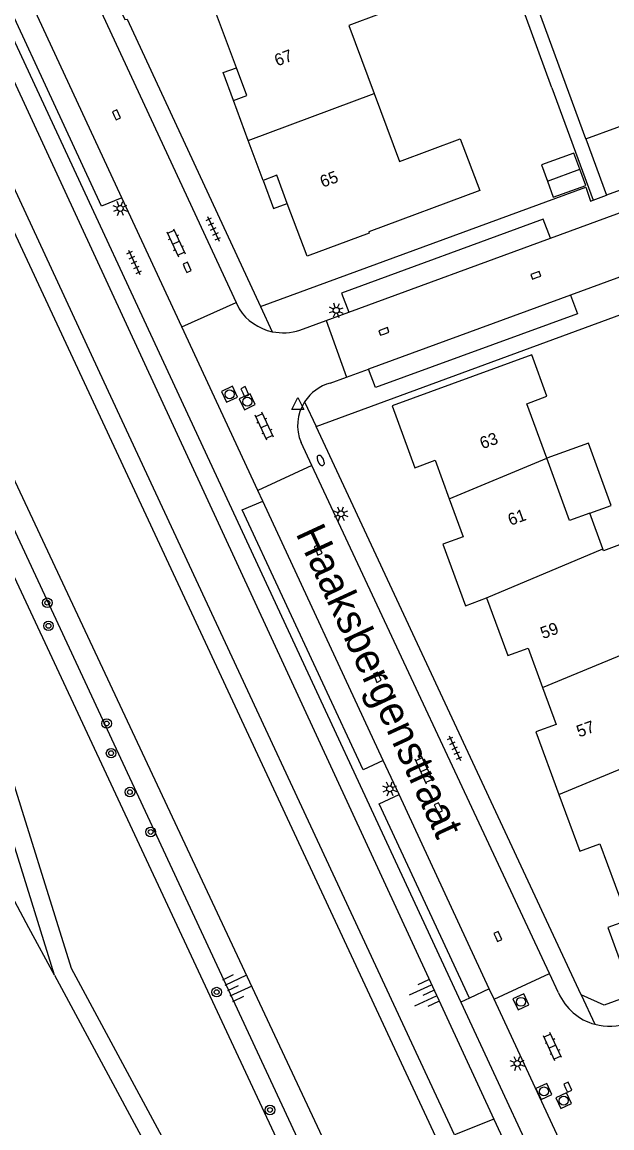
# Model space of a CAD drawing. Extents: x 128000 to 131008, y 398996 to 402500.
# Drawn here: x 128199.6 to 128248.8, y 399087 to 399179.2 of the extents above; entities that cross this region are included whole.
import ezdxf

# ---------------------------------------------------------------- set-up
doc = ezdxf.new("R2010")
doc.units = 0
for name, color, linetype in [('gg-afsc-erfafscheiding', 7, 'Continuous'), ('gg-anno-huisnummerreeks BGT', 7, 'Continuous'), ('gg-anno-openbare ruimte label', 7, 'Continuous'), ('gg-bbg-gedigitaliseerde bebouwing', 7, 'Continuous'), ('gg-bbg-gedigitaliseerde bijgebouw', 7, 'Continuous'), ('gg-bbg-hoofdgebouw', 7, 'Continuous'), ('gg-bbg-luifel en loopbrug', 7, 'Continuous'), ('gg-bbg-tussenscheiding', 7, 'Continuous'), ('gg-knt-BGT kruinlijn', 7, 'Continuous'), ('gg-knt-bovenkant onderkant talud', 7, 'Continuous'), ('gg-knt-verharding', 7, 'Continuous'), ('gg-knt-verharding nz', 7, 'Continuous'), ('gg-kntw-beschoeiing', 7, 'Continuous'), ('gt-grn-groengrens', 7, 'Continuous'), ('gt-grn-weggrens', 7, 'Continuous'), ('gt-symb-boom', 7, 'Continuous'), ('gt-symb-brandkraan', 7, 'Continuous'), ('gt-symb-klinker verharding', 7, 'Continuous'), ('gt-symb-kolk', 7, 'Continuous'), ('gt-symb-lichtmast', 7, 'Continuous'), ('gt-symb-rioolschacht', 7, 'Continuous'), ('gt-symb-talud symbool', 7, 'Continuous'), ('gt-symb-tegel verharding', 7, 'Continuous'), ('gt-symb-waterafsluiter', 7, 'Continuous')]:
    doc.layers.add(name, color=color, linetype=linetype)

# ---------------------------------------------------------------- blocks, each defined once
blk = doc.blocks.new('gt0-KOLK')
at = {"layer": 'gt-symb-kolk'}
blk.add_lwpolyline([(0, 0), (0.375, 0), (0.375, 0.4), (-0.375, 0.4), (-0.375, 0), (0, 0)], dxfattribs=at)
blk = doc.blocks.new('gt0-LMAST')
at = {"layer": 'gt-symb-lichtmast'}
for p, q in [((-0.182, 0.173), (-0.447, 0.438)), ((-0.005, 0.246), (-0.005, 0.621)), ((0.172, 0.173), (0.437, 0.438)), ((-0.255, -0.004), (-0.63, -0.004)), ((-0.182, -0.181), (-0.447, -0.446)), ((-0.005, -0.254), (-0.005, -0.629)), ((0.437, -0.446), (0.172, -0.181)), ((0.245, -0.004), (0.62, -0.004))]:
    blk.add_line(p, q, dxfattribs=at)
blk.add_circle((-0.005, -0.004), 0.25, dxfattribs=at)
blk = doc.blocks.new('gt0-TEG1')
at = {"layer": 'gt-symb-tegel verharding'}
for p, q in [((-1.125, 0), (1.125, 0)), ((-0.9, -0.25), (-0.9, 0.25)), ((-0.45, -0.25), (-0.45, 0.25)), ((0, -0.25), (0, 0.25)), ((0.45, -0.25), (0.45, 0.25)), ((0.9, -0.25), (0.9, 0.25))]:
    blk.add_line(p, q, dxfattribs=at)
blk = doc.blocks.new('gt0-KL1')
at = {"layer": 'gt-symb-klinker verharding'}
for p, q in [((-1.15, 0.3), (1.15, 0.3)), ((-1, -0.3), (-1, 0.3)), ((-0.5, 0.3), (-0.5, 0.45)), ((0, -0.3), (0, 0.3)), ((0.5, 0.3), (0.5, 0.45)), ((1, -0.3), (1, 0.3)), ((-1.15, -0.3), (1.15, -0.3)), ((-0.5, -0.45), (-0.5, -0.3)), ((0.5, -0.45), (0.5, -0.3))]:
    blk.add_line(p, q, dxfattribs=at)
blk = doc.blocks.new('gt0-WAFSL')
at = {"layer": 'gt-symb-waterafsluiter'}
for p, q in [((-0.5, -0.333), (0, 0.667)), ((0, 0.667), (0.5, -0.333)), ((0.5, -0.333), (-0.5, -0.333))]:
    blk.add_line(p, q, dxfattribs=at)
blk = doc.blocks.new('gt0-BR')
at = {"layer": 'gt-symb-brandkraan'}
for centre, radius, start, end in [((-0.244, 0), 0.206, 107.56694, 252.43307), ((0.599, -2.664), 3, 106.89205, 107.56694), ((0, -0.691), 0.938, 73.10799, 106.89205), ((-0.599, -2.664), 3, 72.43309, 73.10799), ((0.244, 0), 0.206, 287.56695, 72.43309), ((0.599, 2.664), 3, 252.43307, 253.10797), ((0, 0.691), 0.938, 253.10797, 286.89206), ((-0.599, 2.664), 3, 286.89206, 287.56695)]:
    blk.add_arc(centre, radius, start, end, dxfattribs=at)
blk = doc.blocks.new('gt0-BOOM')
at = {"layer": 'gt-symb-boom'}
for radius in [0.4, 0.2]:
    blk.add_circle((0, 0), radius, dxfattribs=at)
blk = doc.blocks.new('gt0-TALUD_1')
at = {"layer": 'gt-symb-talud symbool'}
for p, q in [((-1, -1), (-1, 0)), ((-0.5, -2), (-0.5, 0)), ((0.5, -2), (0.5, 0)), ((1, -1), (1, 0)), ((0, -1), (0, 0))]:
    blk.add_line(p, q, dxfattribs=at)
blk = doc.blocks.new('gt0-RS')
at = {"layer": 'gt-symb-rioolschacht'}
blk.add_lwpolyline([(-0.5, -0.5), (0.5, -0.5), (0.5, 0.5), (-0.5, 0.5)], close=True, dxfattribs=at)
blk.add_circle((0, 0), 0.375, dxfattribs=at)

msp = doc.modelspace()

# ---------------------------------------------------------------- linework, layer by layer
at = {"layer": 'gg-afsc-erfafscheiding'}
msp.add_line((128243.803, 399173.757), (128237.819, 399190.149), dxfattribs=at)
at = {"layer": 'gg-bbg-gedigitaliseerde bebouwing'}
for p, q in [((128246.65, 399169.48), (128242.38, 399181.13)), ((128248.06, 399135.288), (128246.974, 399138.253))]:
    msp.add_line(p, q, dxfattribs=at)
for points in [[(128215.841, 399179.87), (128230.31, 399185.17), (128231.926, 399180.85), (128226.865, 399178.956), (128228.988, 399173.282)], [(128228.988, 399173.282), (128231.111, 399167.607), (128236.17, 399169.5)], [(128243.38, 399142.836), (128241.713, 399147.391), (128243.4, 399148.01)], [(128246.974, 399138.253), (128245.285, 399137.634), (128243.38, 399142.836)], [(128251.17, 399127.086), (128249.473, 399131.72), (128251.161, 399132.339), (128249.904, 399135.772), (128248.122, 399135.12), (128248.06, 399135.288)]]:
    msp.add_lwpolyline(points, dxfattribs=at)
at = {"layer": 'gg-bbg-gedigitaliseerde bijgebouw'}
msp.add_line((128243.436, 399165.964), (128246.135, 399166.954), dxfattribs=at)
msp.add_lwpolyline([(128243.436, 399165.964), (128243.931, 399164.614), (128246.63, 399165.605), (128246.135, 399166.954)], dxfattribs=at)
at = {"layer": 'gg-bbg-hoofdgebouw'}
for p, q in [((128217.498, 399175.433), (128215.841, 399179.87)), ((128218.494, 399169.343), (128217.25, 399172.68)), ((128219.73, 399166.03), (128218.494, 399169.343))]:
    msp.add_line(p, q, dxfattribs=at)
for points in [[(128217.25, 399172.68), (128218.37, 399173.1), (128217.498, 399175.433)], [(128246.65, 399169.48), (128251.82, 399171.38), (128251.2, 399173.06), (128254.262, 399174.183)], [(128236.17, 399169.5), (128237.79, 399165.19), (128228.54, 399161.73), (128228.58, 399161.63), (128223.4, 399159.69), (128221.747, 399164.106)], [(128221.747, 399164.106), (128220.87, 399166.45), (128219.73, 399166.03)], [(128243.4, 399148.01), (128242.13, 399151.48), (128230.48, 399147.22), (128232.38, 399142.05), (128234.07, 399142.67), (128235.249, 399139.45)], [(128235.249, 399139.45), (128236.41, 399136.28), (128234.72, 399135.66), (128236.6, 399130.53), (128238.37, 399131.18)], [(128238.37, 399131.18), (128240.13, 399126.38), (128241.82, 399127), (128243.031, 399123.697)], [(128243.031, 399123.697), (128244.16, 399120.62), (128242.48, 399120), (128244.399, 399114.77)], [(128244.399, 399114.77), (128246.13, 399110.05), (128247.81, 399110.67), (128249.08, 399107.223)], [(128249.08, 399107.223), (128250.16, 399104.29), (128248.47, 399103.67), (128250.36, 399098.51), (128261.99, 399102.77), (128260.72, 399106.24)]]:
    msp.add_lwpolyline(points, dxfattribs=at)
at = {"layer": 'gg-bbg-luifel en loopbrug'}
for points in [[(128217.25, 399172.68), (128216.391, 399175.028), (128217.498, 399175.433)], [(128246.135, 399166.954), (128245.639, 399168.304), (128242.94, 399167.313), (128243.436, 399165.964)], [(128219.73, 399166.03), (128220.589, 399163.682), (128221.747, 399164.106)], [(128246.974, 399138.253), (128248.757, 399138.906), (128246.854, 399144.107), (128243.38, 399142.836)]]:
    msp.add_lwpolyline(points, dxfattribs=at)
at = {"layer": 'gg-bbg-tussenscheiding'}
for p, q in [((128218.494, 399169.343), (128228.988, 399173.282)), ((128235.249, 399139.45), (128243.38, 399142.836)), ((128238.37, 399131.18), (128248.06, 399135.288)), ((128243.031, 399123.697), (128251.17, 399127.086)), ((128244.399, 399114.77), (128255.85, 399119.538))]:
    msp.add_line(p, q, dxfattribs=at)
at = {"layer": 'gg-knt-BGT kruinlijn'}
for p, q in [((128191.492, 399190.427), (128238.978, 399087.694)), ((128238.978, 399087.694), (128279.513, 399000))]:
    msp.add_line(p, q, dxfattribs=at)
at = {"layer": 'gg-knt-bovenkant onderkant talud'}
msp.add_line((128183.167, 399170.791), (128262.674, 399000), dxfattribs=at)
at = {"layer": 'gg-knt-verharding'}
for p, q in [((128191.545, 399193.635), (128236.21, 399097.451)), ((128201.79, 399189.651), (128217.472, 399155.834)), ((128243.803, 399173.757), (128247.244, 399164.375)), ((128243.701, 399161.209), (128270.893, 399171.181)), ((128246.65, 399169.48), (128248.371, 399164.789)), ((128272.632, 399166.472), (128245.353, 399156.46)), ((128212.957, 399153.791), (128207.959, 399164.561)), ((128212.957, 399153.791), (128217.472, 399155.834)), ((128217.472, 399155.834), (128217.72, 399155.3)), ((128224.98, 399154.343), (128226.872, 399155.037)), ((128219.283, 399140.159), (128212.957, 399153.791)), ((128222.789, 399153.54), (128224.98, 399154.343)), ((128224.98, 399154.343), (128226.694, 399149.611)), ((128226.694, 399149.611), (128228.525, 399150.283)), ((128225.33, 399149.11), (128226.694, 399149.611)), ((128246.26, 399098.06), (128224.15, 399145.49)), ((128223.785, 399142.227), (128222.89, 399144.141)), ((128223.785, 399142.227), (128219.283, 399140.159)), ((128243.616, 399099.832), (128223.785, 399142.227)), ((128219.699, 399139.263), (128219.283, 399140.159)), ((128231.064, 399114.771), (128229.742, 399117.621)), ((128238.991, 399097.689), (128243.616, 399099.832)), ((128244.37, 399098.22), (128243.616, 399099.832)), ((128238.589, 399098.555), (128236.936, 399097.788)), ((128238.991, 399097.689), (128238.589, 399098.555)), ((128236.21, 399097.451), (128266.633, 399031.936)), ((128246.27, 399082.004), (128238.991, 399097.689))]:
    msp.add_line(p, q, dxfattribs=at)
for points in [[(128209.9, 399209.4), (128204.57, 399187.29), (128208.21, 399179.46), (128208.4, 399179.49), (128219.52, 399155.5)], [(128207.959, 399164.561), (128206.246, 399163.875), (128194.468, 399189.329), (128196.157, 399189.995)], [(128297.29, 399184.08), (128297.73, 399182.91), (128248.371, 399164.789)], [(128219.52, 399155.5), (128246.65, 399165.46), (128247.04, 399164.3), (128247.244, 399164.375)], [(128243.701, 399161.209), (128243.073, 399162.778), (128226.279, 399156.604), (128226.872, 399155.037)], [(128224.15, 399145.49), (128250.4, 399155.13), (128249.96, 399156.32), (128250.173, 399156.398)], [(128245.353, 399156.46), (128245.937, 399154.899), (128229.089, 399148.728), (128228.525, 399150.283)], [(128229.742, 399117.621), (128228.072, 399116.845), (128217.996, 399138.541), (128219.699, 399139.263)], [(128319.553, 399123.408), (128248.18, 399097.19), (128246.26, 399098.06)], [(128236.936, 399097.788), (128229.397, 399113.993), (128231.064, 399114.771)]]:
    msp.add_lwpolyline(points, dxfattribs=at)
for centre, radius, start, end in [((128221.382, 399157.67), 4.362, 212.91261, 258.21263), ((128221.384, 399157.677), 4.369, 258.20897, 288.76362), ((128226.275, 399145.563), 3.67, 104.92131, 147.08239), ((128226.274, 399145.562), 3.67, 147.05317, 202.77874), ((128248.611, 399100.058), 4.622, 203.43542, 254.75023), ((128248.613, 399100.058), 4.622, 254.72282, 290.2015)]:
    msp.add_arc(centre, radius, start, end, dxfattribs=at)
at = {"layer": 'gg-knt-verharding nz'}
for p, q in [((128207.959, 399164.561), (128196.157, 399189.995)), ((128226.872, 399155.037), (128243.701, 399161.209)), ((128245.353, 399156.46), (128228.525, 399150.283)), ((128229.742, 399117.621), (128219.699, 399139.263)), ((128238.589, 399098.555), (128231.064, 399114.771))]:
    msp.add_line(p, q, dxfattribs=at)
at = {"layer": 'gg-kntw-beschoeiing'}
for p, q in [((128186.465, 399188.527), (128234.286, 399085.806)), ((128178.336, 399185.074), (128265.013, 399000))]:
    msp.add_line(p, q, dxfattribs=at)
at = {"layer": 'gt-grn-groengrens'}
for p, q in [((128182.696, 399167.786), (128261.006, 399000)), ((128238.978, 399087.694), (128235.676, 399086.365))]:
    msp.add_line(p, q, dxfattribs=at)
for points in [[(128235.676, 399086.365), (128206.461, 399149.192), (128187.98, 399189.087)], [(128202.329, 399099.701), (128196.74, 399117.612), (128187.083, 399134.894), (128185.219, 399138.903), (128180.193, 399151.385), (128180.136, 399166.973), (128181.87, 399169.157)], [(128181.638, 399166.452), (128181.692, 399151.678), (128186.596, 399139.5), (128188.42, 399135.576), (128198.126, 399118.207), (128203.718, 399100.285), (128215.172, 399079.006), (128219.747, 399070.445), (128231.897, 399047.846), (128235.747, 399040.362), (128257.333, 399000)], [(128202.329, 399099.701), (128200.2, 399103.657), (128198.559, 399106.75)], [(128202.329, 399099.701), (128213.85, 399078.297), (128218.425, 399069.736), (128230.569, 399047.149)]]:
    msp.add_lwpolyline(points, dxfattribs=at)
at = {"layer": 'gt-grn-weggrens'}
for p, q in [((128247.244, 399164.375), (128248.371, 399164.789)), ((128219.52, 399155.5), (128220.491, 399153.4)), ((128223.194, 399147.558), (128224.15, 399145.49)), ((128236.936, 399097.788), (128236.21, 399097.451)), ((128246.26, 399098.06), (128247.395, 399095.599))]:
    msp.add_line(p, q, dxfattribs=at)

# ---------------------------------------------------------------- block references
at = {"layer": 'gt-symb-boom'}
for p in [(128201.733, 399130.777), (128201.832, 399128.854), (128206.679, 399120.701), (128207.054, 399118.222), (128208.622, 399114.979), (128210.357, 399111.65), (128215.861, 399098.286), (128220.303, 399088.45)]:
    msp.add_blockref('gt0-BOOM', p, dxfattribs=at)
at = {"layer": 'gt-symb-brandkraan', "rotation": -65.1007994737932}
msp.add_blockref('gt0-BR', (128224.531, 399142.654), dxfattribs=at)
at = {"layer": 'gt-symb-klinker verharding'}
for p, rotation in [((128212.465, 399160.827), -65.10079947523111), ((128219.828, 399145.508), 114.8992005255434), ((128233.152, 399116.797), 114.89920052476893), ((128243.855, 399093.732), 114.89920052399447)]:
    msp.add_blockref('gt0-KL1', p, dxfattribs=dict(at, rotation=rotation))
at = {"layer": 'gt-symb-kolk'}
for p, rotation in [((128207.314, 399171.418), -65.10079947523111), ((128213.215, 399158.685), -65.10079947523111), ((128242.537, 399157.914), 20.066349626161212), ((128229.875, 399153.234), 20.06634962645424), ((128218.028, 399148.303), -65.10079947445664), ((128224.14, 399135.097), -65.10079947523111), ((128229.063, 399124.476), -65.10079947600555), ((128234.155, 399113.572), -65.1007994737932), ((128239.123, 399102.838), -65.10079947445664), ((128244.957, 399090.267), -65.10079947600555)]:
    msp.add_blockref('gt0-KOLK', p, dxfattribs=dict(at, rotation=rotation))
at = {"layer": 'gt-symb-lichtmast'}
for p, rotation in [((128207.815, 399163.681), -65.1007994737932), ((128225.833, 399155.187), 20.066349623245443), ((128226.224, 399138.194), -65.10079947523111), ((128230.295, 399115.243), -65.10079947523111), ((128240.931, 399092.325), -65.10079947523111)]:
    msp.add_blockref('gt0-LMAST', p, dxfattribs=dict(at, rotation=rotation))
at = {"layer": 'gt-symb-rioolschacht'}
for p, rotation in [((128216.931, 399148.176), -65.10079947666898), ((128218.409, 399147.553), -65.10079947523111), ((128241.231, 399097.473), 114.89920052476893), ((128243.148, 399089.991), -65.1007994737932), ((128244.795, 399089.225), -65.10079947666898)]:
    msp.add_blockref('gt0-RS', p, dxfattribs=dict(at, rotation=rotation))
at = {"layer": 'gt-symb-talud symbool'}
for p, xscale, yscale, rotation in [((128216.756, 399098.388), 0.9998824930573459, 0.999882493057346, 115.02727878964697), ((128233.976, 399098.436), 1.0004319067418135, 1.0004319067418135, -65.17685962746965)]:
    msp.add_blockref('gt0-TALUD_1', p, dxfattribs=dict(at, xscale=xscale, yscale=yscale, rotation=rotation))
at = {"layer": 'gt-symb-tegel verharding', "rotation": -65.10079947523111}
for p in [(128215.579, 399161.981), (128208.981, 399159.184), (128235.709, 399118.644)]:
    msp.add_blockref('gt0-TEG1', p, dxfattribs=at)
at = {"layer": 'gt-symb-waterafsluiter'}
msp.add_blockref('gt0-WAFSL', (128222.631, 399147.241), dxfattribs=at)

# ---------------------------------------------------------------- texts
at = {"layer": 'gg-anno-huisnummerreeks BGT'}
for s, rotation, p in [('67', 20.5, (128220.901, 399175.534)), ('65', 20.5, (128224.701, 399165.408)), ('63', 20.1, (128238.019, 399143.585)), ('61', 20.1, (128240.359, 399137.194)), ('59', 20.2, (128243.071, 399127.737)), ('57', 20.2, (128246.085, 399119.53))]:
    msp.add_text(s, height=1, rotation=rotation, dxfattribs=at).set_placement(p)
at = {"layer": 'gg-anno-openbare ruimte label'}
msp.add_text('Haaksbergenstraat', height=2.5, rotation=294.8, dxfattribs=at).set_placement((128222.41, 399136.576))

doc.saveas('drawing.dxf')
